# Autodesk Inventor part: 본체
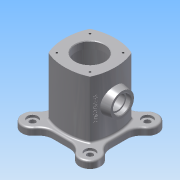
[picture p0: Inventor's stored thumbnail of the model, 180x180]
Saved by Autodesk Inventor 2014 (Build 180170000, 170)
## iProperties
Created: 2016-05
Part Number: 본체
Material: 알루미늄 6061
Document SubType Name: Modeling
Designer: 703-04
Density: 2.71 g/cm^3
Appearance: 알루미늄 - 평지
Mass: 1112.36 g
Surface Area: 862.867 cm^2
Volume: 410.464 cm^3
Author: 703-04
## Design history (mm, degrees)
sketch "스케치1"
  geometry: L1 (-49, -49)-(49, -49); L2 (49, -49)-(49, 49); L3 (49, 49)-(-49, 49); L4 (-49, 49)-(-49, -49); L5 (-49, -49)-(49, 49); L6 (49, -49)-(-49, 49); L7 (0, 0)-(86.341, 86.341); L8 (86.341, 86.341)-(0, 0); L9 (0, 0)-(-73.669, -73.669); L10 (0, 0)-(78.413, -78.413); L11 (0, 0)-(-77.587, 77.587); C1 r 70 at (0, 0); C2 r 18 at (-49, 49); C3 r 18 at (49, 49); C4 r 18 at (49, -49); C5 r 18 at (-49, -49); 1 further point
  constraints: 22 end point, 5 centre point, 5 coincident, 3 perpendicular, 3 point on line, 2 midpoint, 2 parallel, 1 horizontal
  dimensions: "d0" = 98 distance of L1.end L2.end; "d1" = 98 distance of L2.end L3.end; "d2" = 140 diameter of C1; "d3" = 36 diameter of C2; "d4" = 36 diameter of C5; "d5" = 36 diameter of C4; "d6" = 36 diameter of C3
extrude "돌출1" new body sketch "스케치1" distance "d7" = 12; taper "d8" = 0 deg
fillet "모깎기1" dims "d9" = 25
fillet "모깎기2" dims "d10" = 25
sketch "스케치2"
  geometry: A1 r 18 centre (49, 49) between (59.465, 34.355) and (34.355, 59.465) reference; A2 r 18 centre (-49, 49) between (-34.355, 59.465) and (-59.465, 34.355) reference; A3 r 18 centre (-49, -49) between (-59.465, -34.355) and (-34.355, -59.465) reference; A4 r 18 centre (49, -49) between (34.355, -59.465) and (59.465, -34.355) reference; 1 further point
hole "구멍1" sketch "스케치2" at (-49, 49), (49, 49), (49, -49), (-49, -49) diameter "d11" = 10; stored, may be unused: countersink angle "d15" = 90 deg, drill point angle "d17" = 118 deg; dims "d12" = 6, "d13" = 4, "d14" = 2, "d16" = 8
sketch "스케치3"
  geometry: C1 r 5 at (49, -49) reference; C2 r 5 at (-49, 49) reference; C3 r 5 at (49, 49) reference; C4 r 5 at (-49, -49) reference; 1 further point
hole "구멍2" sketch "스케치3" at (-49, 49), (49, 49), (-49, -49), (49, -49) diameter "d18" = 18; stored, may be unused: countersink angle "d22" = 90 deg, drill point angle "d24" = 0 deg; dims "d19" = 6, "d20" = 4, "d21" = 2, "d23" = 4
sketch "스케치4"
  geometry: L1 (-14.014, -49)-(14.014, -49) reference; L2 (0, 0)-(0, 175.452); L3 (0, 0)-(-193.593, 0); L4 (0, 0)-(0, -167.329); L5 (0, 0)-(139.982, 0); L6 (-43, 71.102)-(-43, -80.052); L7 (-79.182, 43)-(71.724, 43); L8 (43, 77.318)-(43, -80.052); L9 (66.752, -43)-(-90.867, -43); L10 (-49, 49)-(49, -49); L11 (49, 49)-(-49, -49); L12 (0, 0)-(-35.355, 35.355); L13 (-49, -49)-(49, 49); L14 (0, 0)-(35.355, -35.355); L15 (-35.355, -35.355)-(0, 0); L16 (0, 0)-(35.355, 35.355); A1 r 18 centre (49, 49) between (59.465, 34.355) and (34.355, 59.465) reference; A2 r 18 centre (-49, 49) between (-34.355, 59.465) and (-59.465, 34.355) reference; A3 r 18 centre (-49, -49) between (-59.465, -34.355) and (-34.355, -59.465) reference; A4 r 18 centre (49, -49) between (34.355, -59.465) and (59.465, -34.355) reference; A5 r 40 centre (0, 0) between (-28.284, 28.284) and (28.284, 28.284); 4 further points; 4 other entities
  constraints: 30 end point, 7 perpendicular, 4 point on circle, 4 point on line, 3 coincident, 1 centre point, 16 other
  dimensions: "d25" = 80 diameter of A5; "d26" = 43 distance between parallel lines of L2 L6; "d27" = 43 distance between parallel lines of L8 L2; "d28" = 43 distance between parallel lines of L3 L9; "d29" = 43 distance between parallel lines of L3 L7; "d31" = 50 distance of L12.end L12.start; "d32" = 45 deg angle of L12 L2; "d33" = 50 distance of L14.end L12.start; "d34" = 45 deg angle of L5 L14; "d35" = 50 distance of L15.start L12.start; "d36" = 45 deg angle of L4 L15; "d37" = 50 distance of L16.end L12.start; "d38" = 45 deg angle of L7 L16
extrude "돌출2" join sketch "스케치4" distance "d39" = 98; taper "d40" = 0 deg
sketch "스케치5"
  geometry: L1 (-35.355, 35.355)-(35.355, -35.355); L2 (35.355, 35.355)-(-35.355, -35.355); A1 r 40 centre (0, 0) between (-28.284, 28.284) and (28.284, 28.284); 3 further points; 1 other entity
  constraints: 4 end point, 4 point on circle, 4 point on line, 1 centre point, 1 coincident, 1 perpendicular, 1 other
  dimensions: "d41" = 80 diameter of A1
hole "구멍3" sketch "스케치5" at (-28.284, 28.284), (28.284, 28.284), (28.284, -28.284), (-28.284, -28.284) diameter "d42" = 3.242; stored, may be unused: countersink angle "d46" = 90 deg, drill point angle "d48" = 118 deg; dims "d43" = 7, "d44" = 4, "d45" = 2, "d47" = 10
sketch "스케치6" dims "d49" = 80
  geometry: L1 (-49, 49)-(49, -49); L2 (49, 49)-(-49, -49); C1 r 5 at (-49, 49) reference; C2 r 5 at (-49, -49) reference; C3 r 1.621 at (28.284, 28.284) reference; C4 r 1.621 at (28.284, -28.284) reference; C5 r 1.621 at (-28.284, -28.284) reference; A1 r 18 centre (49, -49) between (34.355, -59.465) and (59.465, -34.355) reference; A2 r 18 centre (49, 49) between (59.465, 34.355) and (34.355, 59.465) reference; 6 further points
  constraints: 4 coincident, 4 end point, 1 perpendicular, 1 point on line, 3 other
hole "구멍4" sketch "스케치6" at (-28.284, 28.284), (28.284, 28.284), (28.284, -28.284), (-28.284, -28.284) diameter "d50" = 3.242; stored, may be unused: countersink angle "d54" = 90 deg, drill point angle "d56" = 118 deg; dims "d51" = 7, "d52" = 4, "d53" = 2, "d55" = 10
sketch "스케치7"
  geometry: C1 r 25 at (0, 0); 1 further point
  constraints: 1 centre point, 1 coincident
  dimensions: "d57" = 50 diameter of C1
extrude "돌출3" cut sketch "스케치7" distance "d58" = 110; taper "d59" = 0 deg
sketch "스케치9"
  geometry: L1 (35.355, 110)-(-35.355, 110) reference; C1 r 20 at (0, 61); 2 further points
  constraints: 1 centre point, 1 coincident
  dimensions: "d66" = 49 distance from line of point (0, 61) L1; "d67" = 40 diameter of C1
extrude "돌출4" join sketch "스케치9" distance "d68" = 55; taper "d69" = 0 deg
fillet "모깎기3" dims "d80" = 3
fillet "모깎기4" dims "d81" = 3
sketch "스케치8"
  geometry: L1 (0, 12)-(35, 12); L2 (35, 12)-(35, 98); L3 (35, 98)-(0, 98); L4 (-25, 110)-(25, 110) reference; L5 (0, 0)-(0, 136.68); L6 (0, 98)-(0, 12)
  constraints: 10 end point, 2 perpendicular, 2 point on line, 1 horizontal, 1 parallel
  dimensions: "d60" = 12 distance from line of L1 L5.start; "d61" = 12 distance between parallel lines of L3 L4; "d64" = 35 distance between parallel lines of L5 L2
revolve "회전1" sketch "스케치8" stored, may be unused: angle "d65" = 90 deg
fillet "모깎기5" dims "d82" = 3
fillet "모깎기6" dims "d83" = 3
chamfer "모따기1" distance "d84" = 1; stored, may be unused: second distance "d85" = 2, angle "d86" = 45 deg
sketch "스케치13"
  geometry: L1 (36.653, 84.235)-(36.653, 61); L2 (55, 41)-(55, 81) reference; L3 (55, 81)-(36.653, 84.235); L4 (36.653, 61)-(55, 61); L5 (55, 81)-(55, 61); 1 further point
  constraints: 8 end point, 1 collinear, 1 midpoint, 1 vertical
  dimensions: "d90" = 100 deg angle of L1 L3
revolve "회전3" sketch "스케치13" stored, may be unused: angle "d91" = 90 deg
sketch "스케치14"
  geometry: C1 r 20 at (0, 0) reference; C2 r 12.5 at (0, 0); 1 further point
  constraints: 1 centre point, 1 coincident
  dimensions: "d92" = 25 diameter of C2
extrude "돌출7" cut sketch "스케치14" distance "d93" = 55; taper "d94" = 0 deg
sketch "스케치15"
  geometry: C1 r 12.5 at (0, 0) reference; C2 r 20 at (0, 0) reference; C3 r 15 at (0, 0); 1 further point
  constraints: 1 centre point, 1 coincident
  dimensions: "d95" = 30 diameter of C3
extrude "돌출8" cut sketch "스케치15" distance "d96" = 8; taper "d97" = 0 deg
chamfer "모따기3" distance "d98" = 1; stored, may be unused: second distance "d99" = 2, angle "d100" = 45 deg
chamfer "모따기4" distance "d101" = 1; stored, may be unused: second distance "d102" = 2, angle "d103" = 45 deg
fillet "모깎기7" dims "d104" = 3
sketch "스케치16"
  geometry: L1 (-34.353, -49)-(34.353, -49) reference; C1 r 20 at (0, 0) reference; 2 further points
  constraints: 1 other
  dimensions: "d105" = 49 distance from line of L1 point (29, 0); "d106" = 29 distance of point (29, 0) C1.centre
feature "엠보싱1" sketch "스케치16" dims "d0" = 98, "d1" = 98, "d2" = 140, "d3" = 36, "d4" = 36, "d5" = 36, "d6" = 36, "d107" = 0.5, "d108" = 0
node "솔리드1"
